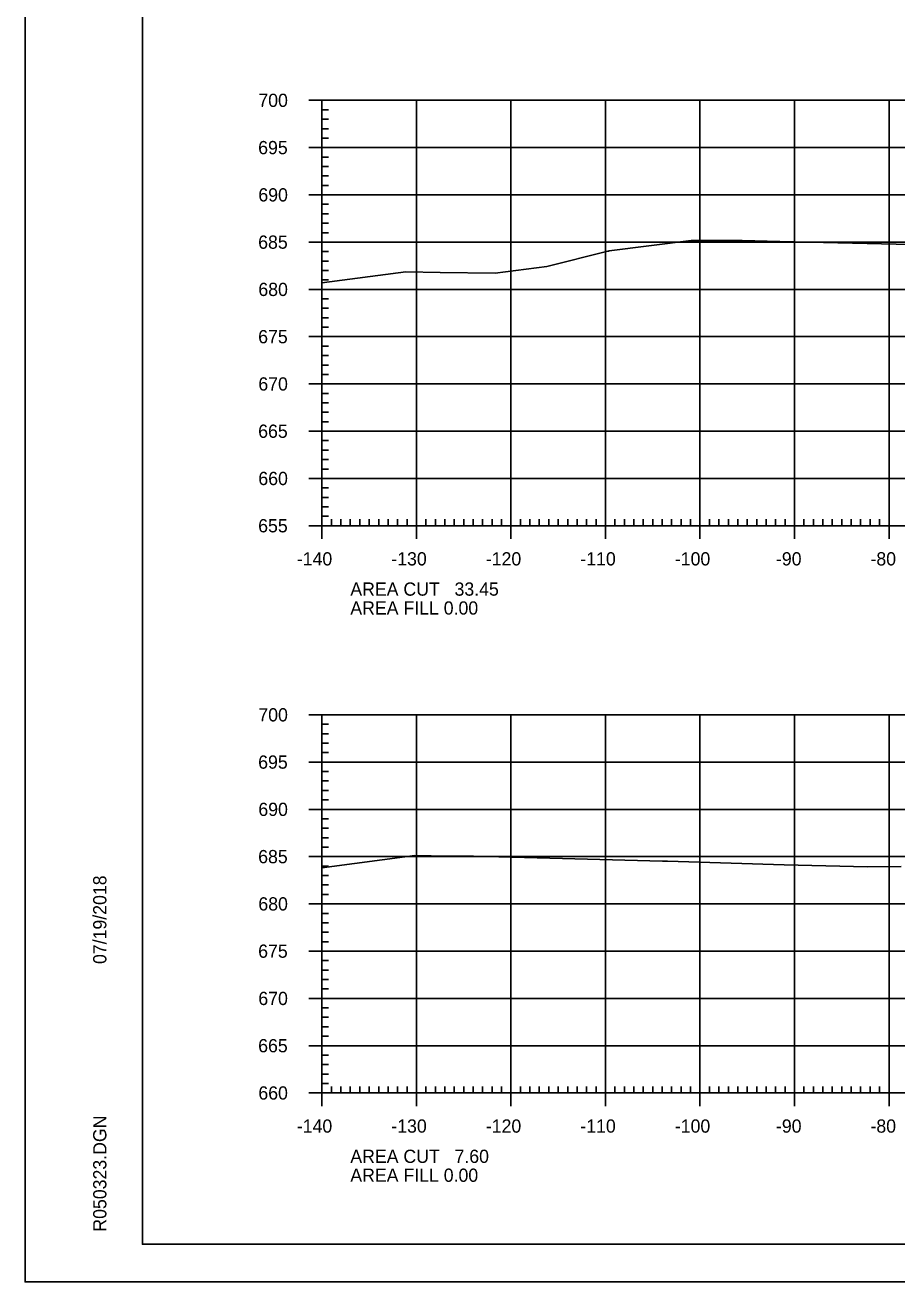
# Model space of a CAD drawing. Extents: x 1360146 to 1361431, y 631444 to 632352.
# Drawn here: x 1361070.2 to 1361162.4, y 631924.1 to 632057 of the extents above; entities that cross this region are included whole.
import ezdxf

# ---------------------------------------------------------------- set-up
doc = ezdxf.new("R2010")
doc.units = 0
for name, color, linetype in [('R_Axis', 7, 'Continuous'), ('R_Axis Annot', 7, 'Continuous'), ('R_Border', 7, 'Continuous'), ('R_Exist Surface', 7, 'Continuous'), ('R_Grid', 7, 'Continuous'), ('R_No Plot', 7, 'Continuous')]:
    doc.layers.add(name, color=color, linetype=linetype)

msp = doc.modelspace()

# ---------------------------------------------------------------- linework, layer by layer
at = {"layer": 'R_Axis'}
for p, q in [((1361100.2, 632049.09), (1361101.6, 632049.09)), ((1361101.6, 632004.09), (1361101.6, 632049.09)), ((1361101.6, 632048.09), (1361102.3, 632048.09)), ((1361101.6, 632047.09), (1361102.3, 632047.09)), ((1361101.6, 632046.09), (1361102.3, 632046.09)), ((1361100.2, 632044.09), (1361101.6, 632044.09)), ((1361101.6, 632045.09), (1361102.3, 632045.09)), ((1361101.6, 632043.09), (1361102.3, 632043.09)), ((1361101.6, 632042.09), (1361102.3, 632042.09)), ((1361101.6, 632041.09), (1361102.3, 632041.09)), ((1361101.6, 632040.09), (1361102.3, 632040.09)), ((1361100.2, 632039.09), (1361101.6, 632039.09)), ((1361101.6, 632038.09), (1361102.3, 632038.09)), ((1361101.6, 632037.09), (1361102.3, 632037.09)), ((1361101.6, 632036.09), (1361102.3, 632036.09)), ((1361101.6, 632035.09), (1361102.3, 632035.09)), ((1361100.2, 632034.09), (1361101.6, 632034.09)), ((1361101.6, 632033.09), (1361102.3, 632033.09)), ((1361101.6, 632032.09), (1361102.3, 632032.09)), ((1361101.6, 632031.09), (1361102.3, 632031.09)), ((1361101.6, 632030.09), (1361102.3, 632030.09)), ((1361100.2, 632029.09), (1361101.6, 632029.09)), ((1361101.6, 632028.09), (1361102.3, 632028.09)), ((1361101.6, 632027.09), (1361102.3, 632027.09)), ((1361101.6, 632026.09), (1361102.3, 632026.09)), ((1361100.2, 632024.09), (1361101.6, 632024.09)), ((1361101.6, 632025.09), (1361102.3, 632025.09)), ((1361101.6, 632023.09), (1361102.3, 632023.09)), ((1361101.6, 632022.09), (1361102.3, 632022.09)), ((1361101.6, 632021.09), (1361102.3, 632021.09)), ((1361101.6, 632020.09), (1361102.3, 632020.09)), ((1361100.2, 632019.09), (1361101.6, 632019.09)), ((1361101.6, 632018.09), (1361102.3, 632018.09)), ((1361101.6, 632017.09), (1361102.3, 632017.09)), ((1361101.6, 632016.09), (1361102.3, 632016.09)), ((1361101.6, 632015.09), (1361102.3, 632015.09)), ((1361100.2, 632014.09), (1361101.6, 632014.09)), ((1361101.6, 632013.09), (1361102.3, 632013.09)), ((1361101.6, 632012.09), (1361102.3, 632012.09)), ((1361101.6, 632011.09), (1361102.3, 632011.09)), ((1361101.6, 632010.09), (1361102.3, 632010.09)), ((1361100.2, 632009.09), (1361101.6, 632009.09)), ((1361101.6, 632008.09), (1361102.3, 632008.09)), ((1361101.6, 632007.09), (1361102.3, 632007.09)), ((1361101.6, 632006.09), (1361102.3, 632006.09)), ((1361100.2, 632004.09), (1361101.6, 632004.09)), ((1361101.6, 632005.09), (1361102.3, 632005.09)), ((1361101.6, 632004.09), (1361381.6, 632004.09)), ((1361101.6, 632002.69), (1361101.6, 632004.09)), ((1361102.6, 632004.09), (1361102.6, 632004.79)), ((1361103.6, 632004.09), (1361103.6, 632004.79)), ((1361104.6, 632004.09), (1361104.6, 632004.79)), ((1361105.6, 632004.09), (1361105.6, 632004.79)), ((1361106.6, 632004.09), (1361106.6, 632004.79)), ((1361107.6, 632004.09), (1361107.6, 632004.79)), ((1361108.6, 632004.09), (1361108.6, 632004.79)), ((1361109.6, 632004.09), (1361109.6, 632004.79)), ((1361110.6, 632004.09), (1361110.6, 632004.79)), ((1361111.6, 632002.69), (1361111.6, 632004.09)), ((1361112.6, 632004.09), (1361112.6, 632004.79)), ((1361113.6, 632004.09), (1361113.6, 632004.79)), ((1361114.6, 632004.09), (1361114.6, 632004.79)), ((1361115.6, 632004.09), (1361115.6, 632004.79)), ((1361116.6, 632004.09), (1361116.6, 632004.79)), ((1361117.6, 632004.09), (1361117.6, 632004.79)), ((1361118.6, 632004.09), (1361118.6, 632004.79)), ((1361119.6, 632004.09), (1361119.6, 632004.79)), ((1361120.6, 632004.09), (1361120.6, 632004.79)), ((1361121.6, 632002.69), (1361121.6, 632004.09)), ((1361122.6, 632004.09), (1361122.6, 632004.79)), ((1361123.6, 632004.09), (1361123.6, 632004.79)), ((1361124.6, 632004.09), (1361124.6, 632004.79)), ((1361125.6, 632004.09), (1361125.6, 632004.79)), ((1361126.6, 632004.09), (1361126.6, 632004.79)), ((1361127.6, 632004.09), (1361127.6, 632004.79)), ((1361128.6, 632004.09), (1361128.6, 632004.79)), ((1361129.6, 632004.09), (1361129.6, 632004.79)), ((1361130.6, 632004.09), (1361130.6, 632004.79)), ((1361131.6, 632002.69), (1361131.6, 632004.09)), ((1361132.6, 632004.09), (1361132.6, 632004.79)), ((1361133.6, 632004.09), (1361133.6, 632004.79)), ((1361134.6, 632004.09), (1361134.6, 632004.79)), ((1361135.6, 632004.09), (1361135.6, 632004.79)), ((1361136.6, 632004.09), (1361136.6, 632004.79)), ((1361137.6, 632004.09), (1361137.6, 632004.79)), ((1361138.6, 632004.09), (1361138.6, 632004.79)), ((1361139.6, 632004.09), (1361139.6, 632004.79)), ((1361140.6, 632004.09), (1361140.6, 632004.79)), ((1361141.6, 632002.69), (1361141.6, 632004.09)), ((1361142.6, 632004.09), (1361142.6, 632004.79)), ((1361143.6, 632004.09), (1361143.6, 632004.79)), ((1361144.6, 632004.09), (1361144.6, 632004.79)), ((1361145.6, 632004.09), (1361145.6, 632004.79)), ((1361146.6, 632004.09), (1361146.6, 632004.79)), ((1361147.6, 632004.09), (1361147.6, 632004.79)), ((1361148.6, 632004.09), (1361148.6, 632004.79)), ((1361149.6, 632004.09), (1361149.6, 632004.79)), ((1361150.6, 632004.09), (1361150.6, 632004.79)), ((1361151.6, 632002.69), (1361151.6, 632004.09)), ((1361152.6, 632004.09), (1361152.6, 632004.79)), ((1361153.6, 632004.09), (1361153.6, 632004.79)), ((1361154.6, 632004.09), (1361154.6, 632004.79)), ((1361155.6, 632004.09), (1361155.6, 632004.79)), ((1361156.6, 632004.09), (1361156.6, 632004.79)), ((1361157.6, 632004.09), (1361157.6, 632004.79)), ((1361158.6, 632004.09), (1361158.6, 632004.79)), ((1361159.6, 632004.09), (1361159.6, 632004.79)), ((1361160.6, 632004.09), (1361160.6, 632004.79)), ((1361161.6, 632002.69), (1361161.6, 632004.09)), ((1361100.2, 631984.09), (1361101.6, 631984.09)), ((1361101.6, 631944.09), (1361101.6, 631984.09)), ((1361101.6, 631983.09), (1361102.3, 631983.09)), ((1361101.6, 631982.09), (1361102.3, 631982.09)), ((1361101.6, 631981.09), (1361102.3, 631981.09)), ((1361101.6, 631980.09), (1361102.3, 631980.09)), ((1361100.2, 631979.09), (1361101.6, 631979.09)), ((1361101.6, 631978.09), (1361102.3, 631978.09)), ((1361101.6, 631977.09), (1361102.3, 631977.09)), ((1361101.6, 631976.09), (1361102.3, 631976.09)), ((1361101.6, 631975.09), (1361102.3, 631975.09)), ((1361100.2, 631974.09), (1361101.6, 631974.09)), ((1361101.6, 631973.09), (1361102.3, 631973.09)), ((1361101.6, 631972.09), (1361102.3, 631972.09)), ((1361101.6, 631971.09), (1361102.3, 631971.09)), ((1361101.6, 631970.09), (1361102.3, 631970.09)), ((1361100.2, 631969.09), (1361101.6, 631969.09)), ((1361101.6, 631968.09), (1361102.3, 631968.09)), ((1361101.6, 631967.09), (1361102.3, 631967.09)), ((1361101.6, 631966.09), (1361102.3, 631966.09)), ((1361100.2, 631964.09), (1361101.6, 631964.09)), ((1361101.6, 631965.09), (1361102.3, 631965.09)), ((1361101.6, 631963.09), (1361102.3, 631963.09)), ((1361101.6, 631962.09), (1361102.3, 631962.09)), ((1361101.6, 631961.09), (1361102.3, 631961.09)), ((1361101.6, 631960.09), (1361102.3, 631960.09)), ((1361100.2, 631959.09), (1361101.6, 631959.09)), ((1361101.6, 631958.09), (1361102.3, 631958.09)), ((1361101.6, 631957.09), (1361102.3, 631957.09)), ((1361101.6, 631956.09), (1361102.3, 631956.09)), ((1361101.6, 631955.09), (1361102.3, 631955.09)), ((1361100.2, 631954.09), (1361101.6, 631954.09)), ((1361101.6, 631953.09), (1361102.3, 631953.09)), ((1361101.6, 631952.09), (1361102.3, 631952.09)), ((1361101.6, 631951.09), (1361102.3, 631951.09)), ((1361101.6, 631950.09), (1361102.3, 631950.09)), ((1361100.2, 631949.09), (1361101.6, 631949.09)), ((1361101.6, 631948.09), (1361102.3, 631948.09)), ((1361101.6, 631947.09), (1361102.3, 631947.09)), ((1361101.6, 631946.09), (1361102.3, 631946.09)), ((1361101.6, 631945.09), (1361102.3, 631945.09)), ((1361102.6, 631944.09), (1361102.6, 631944.79)), ((1361103.6, 631944.09), (1361103.6, 631944.79)), ((1361104.6, 631944.09), (1361104.6, 631944.79)), ((1361105.6, 631944.09), (1361105.6, 631944.79)), ((1361106.6, 631944.09), (1361106.6, 631944.79)), ((1361107.6, 631944.09), (1361107.6, 631944.79)), ((1361108.6, 631944.09), (1361108.6, 631944.79)), ((1361109.6, 631944.09), (1361109.6, 631944.79)), ((1361110.6, 631944.09), (1361110.6, 631944.79)), ((1361112.6, 631944.09), (1361112.6, 631944.79)), ((1361113.6, 631944.09), (1361113.6, 631944.79)), ((1361114.6, 631944.09), (1361114.6, 631944.79)), ((1361115.6, 631944.09), (1361115.6, 631944.79)), ((1361116.6, 631944.09), (1361116.6, 631944.79)), ((1361117.6, 631944.09), (1361117.6, 631944.79)), ((1361118.6, 631944.09), (1361118.6, 631944.79)), ((1361119.6, 631944.09), (1361119.6, 631944.79)), ((1361120.6, 631944.09), (1361120.6, 631944.79)), ((1361122.6, 631944.09), (1361122.6, 631944.79)), ((1361123.6, 631944.09), (1361123.6, 631944.79)), ((1361124.6, 631944.09), (1361124.6, 631944.79)), ((1361125.6, 631944.09), (1361125.6, 631944.79)), ((1361126.6, 631944.09), (1361126.6, 631944.79)), ((1361127.6, 631944.09), (1361127.6, 631944.79)), ((1361128.6, 631944.09), (1361128.6, 631944.79)), ((1361129.6, 631944.09), (1361129.6, 631944.79)), ((1361130.6, 631944.09), (1361130.6, 631944.79)), ((1361132.6, 631944.09), (1361132.6, 631944.79)), ((1361133.6, 631944.09), (1361133.6, 631944.79)), ((1361134.6, 631944.09), (1361134.6, 631944.79)), ((1361135.6, 631944.09), (1361135.6, 631944.79)), ((1361136.6, 631944.09), (1361136.6, 631944.79)), ((1361137.6, 631944.09), (1361137.6, 631944.79)), ((1361138.6, 631944.09), (1361138.6, 631944.79)), ((1361139.6, 631944.09), (1361139.6, 631944.79)), ((1361140.6, 631944.09), (1361140.6, 631944.79)), ((1361142.6, 631944.09), (1361142.6, 631944.79)), ((1361143.6, 631944.09), (1361143.6, 631944.79)), ((1361144.6, 631944.09), (1361144.6, 631944.79)), ((1361145.6, 631944.09), (1361145.6, 631944.79)), ((1361146.6, 631944.09), (1361146.6, 631944.79)), ((1361147.6, 631944.09), (1361147.6, 631944.79)), ((1361148.6, 631944.09), (1361148.6, 631944.79)), ((1361149.6, 631944.09), (1361149.6, 631944.79)), ((1361150.6, 631944.09), (1361150.6, 631944.79)), ((1361152.6, 631944.09), (1361152.6, 631944.79)), ((1361153.6, 631944.09), (1361153.6, 631944.79)), ((1361154.6, 631944.09), (1361154.6, 631944.79)), ((1361155.6, 631944.09), (1361155.6, 631944.79)), ((1361156.6, 631944.09), (1361156.6, 631944.79)), ((1361157.6, 631944.09), (1361157.6, 631944.79)), ((1361158.6, 631944.09), (1361158.6, 631944.79)), ((1361159.6, 631944.09), (1361159.6, 631944.79)), ((1361160.6, 631944.09), (1361160.6, 631944.79)), ((1361100.2, 631944.09), (1361101.6, 631944.09)), ((1361101.6, 631944.09), (1361381.6, 631944.09)), ((1361101.6, 631942.69), (1361101.6, 631944.09)), ((1361111.6, 631942.69), (1361111.6, 631944.09)), ((1361121.6, 631942.69), (1361121.6, 631944.09)), ((1361131.6, 631942.69), (1361131.6, 631944.09)), ((1361141.6, 631942.69), (1361141.6, 631944.09)), ((1361151.6, 631942.69), (1361151.6, 631944.09)), ((1361161.6, 631942.69), (1361161.6, 631944.09))]:
    msp.add_line(p, q, dxfattribs=at)
at = {"layer": 'R_Border'}
for p, q in [((1361082.6, 631928.09), (1361082.6, 632133.55)), ((1361082.6, 631928.09), (1361082.6, 631928.09)), ((1361398.78, 631928.09), (1361082.6, 631928.09))]:
    msp.add_line(p, q, dxfattribs=at)
at = {"layer": 'R_Exist Surface'}
for points in [[(1361101.6, 632029.8), (1361110.47, 632030.95), (1361114.11, 632030.89), (1361119.93, 632030.79), (1361125.41, 632031.52), (1361131.85, 632033.14), (1361131.9, 632033.15), (1361131.93, 632033.15), (1361132, 632033.16), (1361140.67, 632034.26), (1361142.4, 632034.25), (1361146.05, 632034.25), (1361150.06, 632034.15), (1361156.19, 632034), (1361162.36, 632033.87), (1361166.66, 632033.79)], [(1361101.6, 631967.92), (1361111.44, 631969.21), (1361113.16, 631969.16), (1361115.58, 631969.14), (1361117.63, 631969.13), (1361125.72, 631968.92), (1361137.64, 631968.62), (1361137.86, 631968.62), (1361138.17, 631968.61), (1361150.49, 631968.23), (1361159.33, 631968), (1361162.87, 631968.05)]]:
    msp.add_lwpolyline(points, dxfattribs=at)
at = {"layer": 'R_Grid'}
for p, q in [((1361101.6, 632049.09), (1361381.6, 632049.09)), ((1361101.6, 632004.09), (1361101.6, 632049.09)), ((1361111.6, 632004.09), (1361111.6, 632049.09)), ((1361121.6, 632004.09), (1361121.6, 632049.09)), ((1361131.6, 632004.09), (1361131.6, 632049.09)), ((1361141.6, 632004.09), (1361141.6, 632049.09)), ((1361151.6, 632004.09), (1361151.6, 632049.09)), ((1361161.6, 632004.09), (1361161.6, 632049.09)), ((1361101.6, 632044.09), (1361381.6, 632044.09)), ((1361101.6, 632039.09), (1361381.6, 632039.09)), ((1361101.6, 632034.09), (1361381.6, 632034.09)), ((1361101.6, 632029.09), (1361381.6, 632029.09)), ((1361101.6, 632024.09), (1361381.6, 632024.09)), ((1361101.6, 632019.09), (1361381.6, 632019.09)), ((1361101.6, 632014.09), (1361381.6, 632014.09)), ((1361101.6, 632009.09), (1361381.6, 632009.09)), ((1361101.6, 632004.09), (1361381.6, 632004.09)), ((1361101.6, 631984.09), (1361381.6, 631984.09)), ((1361101.6, 631944.09), (1361101.6, 631984.09)), ((1361111.6, 631944.09), (1361111.6, 631984.09)), ((1361121.6, 631944.09), (1361121.6, 631984.09)), ((1361131.6, 631944.09), (1361131.6, 631984.09)), ((1361141.6, 631944.09), (1361141.6, 631984.09)), ((1361151.6, 631944.09), (1361151.6, 631984.09)), ((1361161.6, 631944.09), (1361161.6, 631984.09)), ((1361101.6, 631979.09), (1361381.6, 631979.09)), ((1361101.6, 631974.09), (1361381.6, 631974.09)), ((1361101.6, 631969.09), (1361381.6, 631969.09)), ((1361101.6, 631964.09), (1361381.6, 631964.09)), ((1361101.6, 631959.09), (1361381.6, 631959.09)), ((1361101.6, 631954.09), (1361381.6, 631954.09)), ((1361101.6, 631949.09), (1361381.6, 631949.09)), ((1361101.6, 631944.09), (1361381.6, 631944.09))]:
    msp.add_line(p, q, dxfattribs=at)
at = {"layer": 'R_No Plot'}
msp.add_line((1361070.2, 631924.11), (1361403.53, 631924.11), dxfattribs=at)
for points in [[(1361070.19, 632137.45), (1361403.53, 632137.45), (1361403.53, 631924.11), (1361070.19, 631924.11)], [(1361316.52, 632133.55), (1361316.52, 632123.67), (1361352.25, 632123.67), (1361352.25, 632120.75), (1361375.45, 632120.75), (1361375.45, 632096.42), (1361398.78, 632096.42), (1361398.78, 631928.09), (1361082.6, 631928.09), (1361082.6, 632133.55)]]:
    msp.add_lwpolyline(points, close=True, dxfattribs=at)

# ---------------------------------------------------------------- texts
at = {"layer": 'R_Axis Annot'}
for s, p in [('700', (1361094.87, 632048.39)), ('695', (1361094.85, 632043.39)), ('690', (1361094.87, 632038.39)), ('685', (1361094.85, 632033.39)), ('680', (1361094.87, 632028.39)), ('675', (1361094.85, 632023.39)), ('670', (1361094.87, 632018.39)), ('665', (1361094.85, 632013.39)), ('660', (1361094.87, 632008.39)), ('655', (1361094.85, 632003.39)), ('-140', (1361098.94, 631999.89)), ('-130', (1361108.94, 631999.89)), ('-120', (1361118.94, 631999.89)), ('-110', (1361128.94, 631999.89)), ('-100', (1361138.94, 631999.89)), ('-90', (1361149.64, 631999.89)), ('-80', (1361159.64, 631999.89)), ('AREA CUT   33.45', (1361104.6, 631996.69)), ('AREA FILL 0.00', (1361104.6, 631994.69)), ('700', (1361094.87, 631983.39)), ('695', (1361094.85, 631978.39)), ('690', (1361094.87, 631973.39)), ('685', (1361094.85, 631968.39)), ('680', (1361094.87, 631963.39)), ('675', (1361094.85, 631958.39)), ('670', (1361094.87, 631953.39)), ('665', (1361094.85, 631948.39)), ('660', (1361094.87, 631943.39)), ('-140', (1361098.94, 631939.89)), ('-130', (1361108.94, 631939.89)), ('-120', (1361118.94, 631939.89)), ('-110', (1361128.94, 631939.89)), ('-100', (1361138.94, 631939.89)), ('-90', (1361149.64, 631939.89)), ('-80', (1361159.64, 631939.89)), ('AREA CUT   7.60', (1361104.6, 631936.69)), ('AREA FILL 0.00', (1361104.6, 631934.69))]:
    msp.add_text(s, height=1.4, dxfattribs=at).set_placement(p)
at = {"layer": 'R_Border'}
for s, p in [('07/19/2018', (1361078.79, 631957.73)), ('R050323.DGN', (1361078.79, 631929.42))]:
    msp.add_text(s, height=1.4, rotation=90, dxfattribs=at).set_placement(p)

doc.saveas('drawing.dxf')
